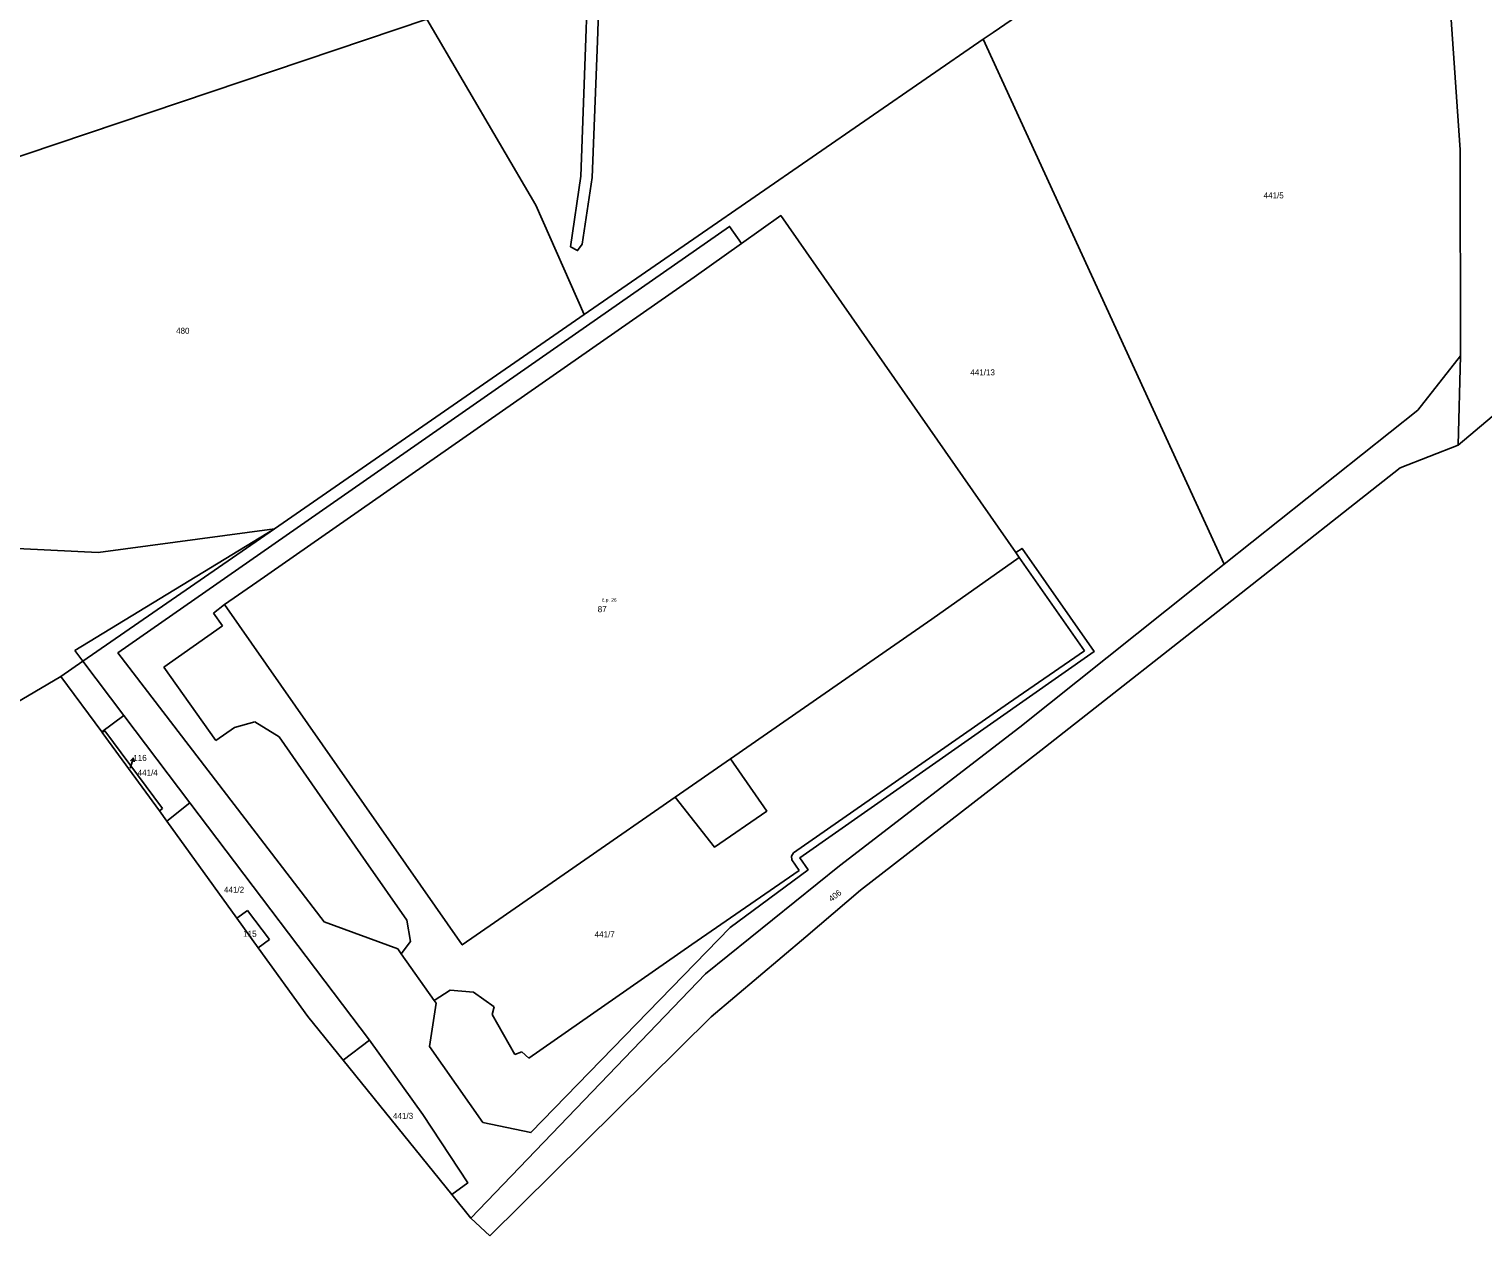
# Model space of a CAD drawing. Extents: x -880531 to -877616, y -1023932 to -1021350.
# Drawn here: x -879914.9 to -879503.7, y -1023540 to -1023198.6 of the extents above; entities that cross this region are included whole.
import ezdxf

# ---------------------------------------------------------------- set-up
doc = ezdxf.new("R2010")
doc.units = 0
for name, color, linetype in [('Definiční body', 7, 'Continuous'), ('Hranice parcel', 7, 'Continuous'), ('Parcelní čísla', 7, 'Continuous'), ('Polygon budovy', 7, 'Continuous'), ('Pop  PČ popisy', 7, 'Continuous'), ('Vnitřní kresba', 7, 'Continuous')]:
    doc.layers.add(name, color=color, linetype=linetype)

msp = doc.modelspace()

# ---------------------------------------------------------------- linework, layer by layer
at = {"layer": 'Hranice parcel'}
for p, q in [((-879757.93, -1023279.39), (-879644.99, -1023201.47)), ((-879644.99, -1023201.47), (-879576.82, -1023349.94)), ((-879510.7, -1023316.27), (-879509.95, -1023291)), ((-879484.27, -1023294.03), (-879510.7, -1023316.27)), ((-879899.74, -1023377.45), (-879905.93, -1023381.73)), ((-879894.39, -1023397.43), (-879905.93, -1023381.73)), ((-879894.26, -1023397.6), (-879894.39, -1023397.43)), ((-879894.26, -1023397.6), (-879893.55, -1023397.08)), ((-879882.93, -1023413.02), (-879894.26, -1023397.6)), ((-879893.55, -1023397.08), (-879877.22, -1023419.07)), ((-879878.09, -1023419.72), (-879882.93, -1023413.02)), ((-879869.43, -1023417.48), (-879876, -1023422.62)), ((-879818.61, -1023484.6), (-879869.43, -1023417.48)), ((-879877.22, -1023419.07), (-879878.09, -1023419.72)), ((-879876, -1023422.62), (-879878.09, -1023419.72)), ((-879856.13, -1023450.14), (-879876, -1023422.62)), ((-879679.71, -1023442.22), (-879695.24, -1023455.36)), ((-879856.13, -1023450.14), (-879853.12, -1023447.89)), ((-879850.09, -1023458.51), (-879856.13, -1023450.14)), ((-879853.12, -1023447.89), (-879846.97, -1023456.15)), ((-879846.97, -1023456.15), (-879850.09, -1023458.51)), ((-879826.13, -1023490.23), (-879818.61, -1023484.6)), ((-879795.36, -1023528.3), (-879826.13, -1023490.23)), ((-879789.99, -1023534.94), (-879795.36, -1023528.3)), ((-879784.57, -1023539.98), (-879789.99, -1023534.94))]:
    msp.add_line(p, q, dxfattribs=at)
for points in [[(-879708.92, -1022929.76), (-879721.2, -1022953.88), (-879726.57, -1022964.2), (-879743.8, -1022997.19), (-879746.1, -1023011.86), (-879748.46, -1023048.19), (-879751.26, -1023123.02), (-879751.84, -1023140.9), (-879752.54, -1023154.07), (-879754.09, -1023202.09), (-879755.63, -1023240.59), (-879758.43, -1023259.5), (-879759.78, -1023261.27), (-879761.74, -1023260.17), (-879758.89, -1023240.26), (-879755.74, -1023154.38), (-879753.93, -1023107.21), (-879752.19, -1023050.58), (-879749.56, -1023013.98), (-879747.01, -1022996.88), (-879731.3, -1022966.33), (-879727.7, -1022959.9), (-879712.9, -1022928.63)], [(-880077.12, -1023065.31), (-880055.22, -1023067.87), (-880041.66, -1023106.22), (-880029.62, -1023146.23), (-880004.11, -1023215.22), (-879985.57, -1023257.44), (-879802.44, -1023195.78)], [(-879644.99, -1023201.47), (-879642.22, -1023199.58), (-879527.34, -1023120.75)], [(-879509.95, -1023291), (-879510.06, -1023232.76), (-879512.71, -1023194.62), (-879521.84, -1023140.03), (-879527.34, -1023120.75)], [(-879802.44, -1023195.78), (-879771.56, -1023248.4), (-879757.93, -1023279.39)], [(-879713.41, -1023259.28), (-879702.28, -1023251.38), (-879635.79, -1023346.7)], [(-879635.79, -1023346.7), (-879634.03, -1023345.51), (-879613.61, -1023374.66), (-879696.85, -1023433.03), (-879694.58, -1023436.42), (-879716.61, -1023452.76), (-879772.97, -1023510.77), (-879786.54, -1023507.87), (-879801.63, -1023486.43), (-879799.75, -1023474.18), (-879800.3, -1023473.4), (-879809.64, -1023460.17), (-879810.66, -1023458.74), (-879831.49, -1023451.15), (-879889.82, -1023375.09), (-879716.78, -1023254.43), (-879713.41, -1023259.28)], [(-879713.41, -1023259.28), (-879726.78, -1023268.77), (-879850.48, -1023355.02), (-879859.64, -1023361.41), (-879792.42, -1023457.65), (-879783.3, -1023451.36), (-879732.12, -1023415.84), (-879721.06, -1023429.99), (-879706.27, -1023419.83), (-879716.52, -1023405.01), (-879659.57, -1023365.49), (-879634.84, -1023348.06), (-879635.79, -1023346.7)], [(-879899.74, -1023377.45), (-879845.54, -1023339.97), (-879757.93, -1023279.39)], [(-879509.95, -1023291), (-879522.11, -1023306.43), (-879576.82, -1023349.94)], [(-879510.7, -1023316.27), (-879527.07, -1023322.71), (-879572, -1023358.18), (-879628.71, -1023402.65), (-879679.71, -1023442.22)], [(-879905.93, -1023381.73), (-879935.49, -1023399.11), (-879976.2, -1023345.78)], [(-879576.82, -1023349.94), (-879634.66, -1023396.1), (-879685.66, -1023435.29), (-879723.58, -1023465.86), (-879789.99, -1023534.94)], [(-879869.43, -1023417.48), (-879888.15, -1023392.77), (-879899.74, -1023377.45)], [(-879826.13, -1023490.23), (-879836.07, -1023477.93), (-879850.09, -1023458.51)], [(-879695.24, -1023455.36), (-879721.96, -1023477.97), (-879784.57, -1023539.98)], [(-879795.36, -1023528.3), (-879790.86, -1023525.01), (-879803.53, -1023505.65), (-879818.61, -1023484.6)]]:
    msp.add_lwpolyline(points, dxfattribs=at)
at = {"layer": 'Polygon budovy'}
msp.add_lwpolyline([(-879850.48, -1023355.02), (-879859.64, -1023361.41), (-879792.42, -1023457.65), (-879783.3, -1023451.36), (-879732.12, -1023415.84), (-879716.52, -1023405.01), (-879659.57, -1023365.49), (-879634.84, -1023348.06), (-879635.79, -1023346.7), (-879702.28, -1023251.38), (-879713.41, -1023259.28), (-879726.78, -1023268.77)], close=True, dxfattribs=at)
at = {"layer": 'Pop  PČ popisy'}
for p, q in [((-879886.31, -1023407.65), (-879885.433, -1023404.78)), ((-879885.433, -1023404.78), (-879886.204, -1023405.591)), ((-879885.433, -1023404.78), (-879885.247, -1023405.884))]:
    msp.add_line(p, q, dxfattribs=at)
at = {"layer": 'Vnitřní kresba'}
for p, q in [((-879902.03, -1023374.43), (-879845.54, -1023339.97)), ((-879895.38, -1023346.64), (-879845.54, -1023339.97)), ((-879947.71, -1023344.11), (-879895.38, -1023346.64)), ((-879634.84, -1023348.06), (-879616.4, -1023374.49)), ((-879862.78, -1023363.8), (-879859.64, -1023361.41)), ((-879862.78, -1023363.8), (-879860.18, -1023367.39)), ((-879876.79, -1023379.08), (-879860.18, -1023367.39)), ((-879902.03, -1023374.43), (-879899.74, -1023377.45)), ((-879637.82, -1023389.31), (-879616.4, -1023374.49)), ((-879876.79, -1023379.08), (-879862.13, -1023399.89)), ((-879894.39, -1023397.43), (-879888.15, -1023392.77)), ((-879698.7, -1023431.58), (-879637.82, -1023389.31)), ((-879862.13, -1023399.89), (-879856.82, -1023396.21)), ((-879856.82, -1023396.21), (-879851.08, -1023394.58)), ((-879851.08, -1023394.58), (-879844.19, -1023398.78)), ((-879844.19, -1023398.78), (-879819.7, -1023434.1)), ((-879732.12, -1023415.84), (-879716.52, -1023405.01)), ((-879699.26, -1023432.58), (-879698.7, -1023431.58)), ((-879699.26, -1023432.58), (-879699.15, -1023433.6)), ((-879699.15, -1023433.6), (-879697.12, -1023436.6)), ((-879819.7, -1023434.1), (-879808.06, -1023450.68)), ((-879727.44, -1023457.58), (-879697.12, -1023436.6)), ((-879808.06, -1023450.68), (-879807.05, -1023456.71)), ((-879809.64, -1023460.17), (-879807.05, -1023456.71)), ((-879773.52, -1023489.7), (-879727.44, -1023457.58)), ((-879800.3, -1023473.4), (-879795.8, -1023470.44)), ((-879795.8, -1023470.44), (-879789.2, -1023471.03)), ((-879789.2, -1023471.03), (-879783.37, -1023475.23)), ((-879783.94, -1023477.38), (-879783.37, -1023475.23)), ((-879783.94, -1023477.38), (-879777.54, -1023488.66)), ((-879777.54, -1023488.66), (-879775.58, -1023487.88)), ((-879775.58, -1023487.88), (-879773.52, -1023489.7))]:
    msp.add_line(p, q, dxfattribs=at)

# ---------------------------------------------------------------- texts
at = {"layer": 'Definiční body'}
msp.add_text('č.p. 26', height=1, dxfattribs=at).set_placement((-879752.88, -1023360.61))
at = {"layer": 'Parcelní čísla'}
for s, p in [('441/5', (-879565.69, -1023246.52)), ('480', (-879873.35, -1023284.82)), ('441/13', (-879648.67, -1023296.58)), ('87', (-879754.07, -1023363.55)), ('116', (-879885.46, -1023405.62)), ('441/4', (-879884.23, -1023409.81)), ('441/2', (-879859.8, -1023442.92)), ('115', (-879854.363, -1023455.38)), ('441/7', (-879754.95, -1023455.52)), ('441/3', (-879811.98, -1023506.87))]:
    msp.add_text(s, height=1.7, dxfattribs=at).set_placement(p)
msp.add_text('406', height=1.7, rotation=38, dxfattribs=at).set_placement((-879687.916, -1023445.559))

doc.saveas('drawing.dxf')
